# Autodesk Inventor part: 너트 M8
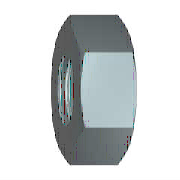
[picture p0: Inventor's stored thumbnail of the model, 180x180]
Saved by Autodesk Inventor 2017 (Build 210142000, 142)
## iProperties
IsCustomPart: 1
Created: 2012-02
Part Number: 너트 M8
Material: 강철, 연강
Description: 6각 너트 및 6각 가는 너트
Document SubType Name: Modeling
Standard: KS B 1012
Designer: mduedu
Standards Organization: KS
Language: ko-KR
Size Designation: M 8
Categories: <MemberInstance><Categories><Category DisplayName="조임쇠" InternalName="e4da775c-781d-43d5-af7c-5136215cf5a6" Mnemonic="FSTN"><Category DisplayName="너트" InternalN
Density: 7.86 g/cm^3
Mass: 4.30432 g
Surface Area: 5.27675 cm^2
Volume: 0.547623 cm^3
Appearance: 강철
Author: mduedu
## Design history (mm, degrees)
sketch "스케치1"
  geometry: L1 (-7.506, 0)-(-3.753, 6.5); L2 (-3.753, 6.5)-(3.753, 6.5); L3 (3.753, 6.5)-(7.506, 0); L4 (7.506, 0)-(3.753, -6.5); L5 (3.753, -6.5)-(-3.753, -6.5); L6 (-3.753, -6.5)-(-7.506, 0); 2 further points
  constraints: 12 end point, 1 coincident, 1 horizontal, 11 other
  dimensions: "d0" = 15.01111 distance of L3.end L1.start (= 1.1547 x SW)
extrude "본체" new body sketch "스케치1" distance "d1" = 5 (= KOH); taper "d2" = 0 deg
sketch "스케치2"
  geometry: L1 (0, 3.753)-(0, 7.506) reference; L2 (0, 7.506)-(5, 7.506) reference; L3 (5, 3.753)-(5, 7.506) reference; L4 (-1, 0)-(6, 0) reference; L5 (0.581, 7.506)-(0, 6.5); L6 (4.419, 7.506)-(5, 6.5)
  constraints: 4 end point, 4 point on line
  dimensions: "d3" = 30 deg angle of L1 L5 (= ANG1); "d4" = 30 deg angle of L3 L6 (= ANG2); "d5" = 13 diameter of L5.end L4 (= SW0); "d6" = 13 diameter of L6.end L4 (= SW01)
revolve "모따기1" sketch "스케치2" stored, may be unused: angle "d7" = 90 deg
sketch "스케치3"
  geometry: A1 r 6.5 centre (0, 0) between (-3.25, -5.629) and (3.25, -5.629) reference; 1 further point
  constraints: 1 coincident
hole "스레드" sketch "스케치3" at (0, 0) diameter "d25" = 6.647; stored, may be unused: countersink angle "d29" = 82 deg, drill point angle "d31" = 118 deg; dims "d26" = 6, "d27" = 4, "d28" = 2, "d30" = 8
workaxis "Work Axis1"
workplane "Work Plane1"
body "Solid1"
chamfer "모따기2" distance "d8" = 0.67658 (= -0.5 x GD1 + 0.5 x NND); stored, may be unused: angle "d9" = 30 deg, second distance "d40" = 0.67658 (= -0.5 x GD1 + 0.5 x NND)
chamfer "모따기3" distance "d10" = 0.67658 (= -0.5 x GD1 + 0.5 x NND); stored, may be unused: angle "d11" = 30 deg, second distance "d41" = 0.67658 (= -0.5 x GD1 + 0.5 x NND)
other parameters: "ANG1" = 30 deg [user parameter; used in 1 equation term], "ANG2" = 30 deg [user parameter; used in 1 equation term], "NND" = 8 [user parameter; used in 4 equation terms], "KOH" = 5 [user parameter; used in 1 equation term], "SW" = 13 [user parameter; used in 4 equation terms], "SW0" = 13 (= SW) [user parameter; used in 1 equation term], "SW01" = 13 (= SW) [user parameter; used in 1 equation term], "GD1" = 6.64684 (computed from THREADDIA, PTC, TOA) [user parameter; used in 4 equation terms], "d13" = 0, "d14" = 0, "d39" = 0, "d42" = 0, "GUL" = 0.67658 (= 0.541266 x PTC) [user parameter], "TPU" = 8 (computed from PTC) [user parameter], "THREADDIA" = 8 [user parameter; used in 1 equation term], "TOA" = 30 deg [user parameter; used in 1 equation term], "PTC" = 1.25 [user parameter; used in 4 equation terms], "E0" = 15.015 (= 1.155 x SW) [user parameter], "GAL" = 0.67658 (= 0.541266 x PTC) [user parameter]
